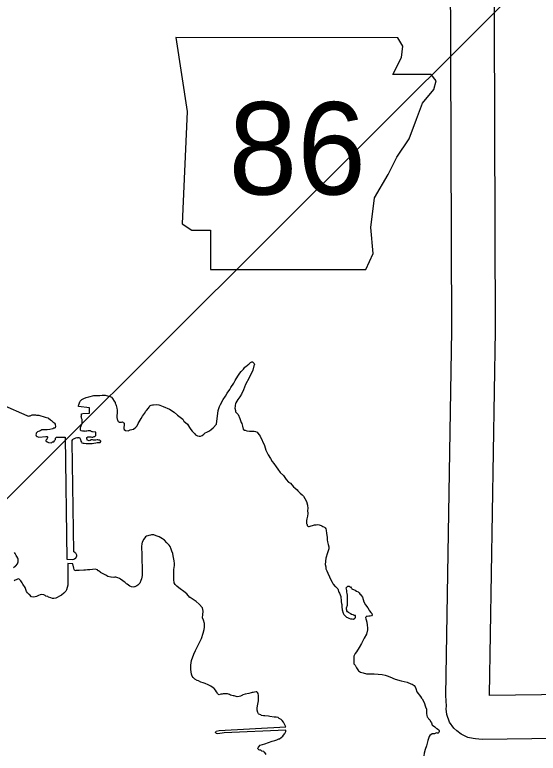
# Model space of a CAD drawing. Extents: x 982240 to 1103002, y 974866 to 1054902.
# Drawn here: x 993089 to 995781, y 1041155 to 1044953 of the extents above; entities that cross this region are included whole.
import ezdxf

# ---------------------------------------------------------------- set-up
doc = ezdxf.new("R2010")
doc.units = 0
for name, color, linetype in [('Level 10', 7, 'Continuous'), ('Level 21', 7, 'Continuous'), ('Level 9', 7, 'Continuous'), ('R_Draft', 7, 'Continuous')]:
    doc.layers.add(name, color=color, linetype=linetype)

msp = doc.modelspace()

# ---------------------------------------------------------------- linework, layer by layer
at = {"layer": 'Level 10'}
for points in [[(997535, 1041478.4), (995530.7, 1041452), (995530.5, 1041456.3), (995561.7, 1043327.4), (995554.8, 1045449.5), (993532.3, 1045386), (993520.8, 1047196.5), (993518.6, 1047217.1), (993510.8, 1047255.6), (993504, 1047271.4), (993498.3, 1047283.7), (993481.2, 1047311.6), (993449.8, 1047336.3), (993440.9, 1047341.2), (993427, 1047349.4), (993401.8, 1047358.6), (993378.8, 1047363.2), (993360.9, 1047365.2), (993338.6, 1047366.7), (991537.1, 1047360.6)], [(997538, 1041253.4), (995492.8, 1041226.5), (995458.9, 1041229.1), (995446.6, 1041230.3), (995419.3, 1041235.5), (995385.3, 1041252.6), (995363.1, 1041270), (995347.6, 1041284.6), (995324.5, 1041314.5), (995311.1, 1041353.8), (995307.9, 1041384.2), (995308.4, 1041397.6), (995305.3, 1041451.7), (995336.6, 1043328.9), (995330.6, 1045217.4), (993308.8, 1045153.9), (993296.2, 1047141.5), (991536.7, 1047135.6)]]:
    msp.add_lwpolyline(points, dxfattribs=at)
at = {"layer": 'Level 21'}
msp.add_lwpolyline([(993917.4, 1044835.9), (993974.5, 1044455.2), (993949.1, 1043877.9), (993999.9, 1043846.2), (994095, 1043846.2), (994095, 1043643.2), (994894.4, 1043643.2), (994932.5, 1043725.6), (994919.8, 1043858.9), (994938.8, 1044011.1), (995008.6, 1044131.7), (995053, 1044220.5), (995116.5, 1044315.7), (995154.5, 1044417.2), (995186.2, 1044499.6), (995243.3, 1044569.4), (995256, 1044613.8), (995230.7, 1044645.6), (995034, 1044645.6), (995078.4, 1044734.4), (995084.7, 1044791.5), (995058.4, 1044835.3)], close=True, dxfattribs=at)
at = {"layer": 'Level 9'}
for points in [[(993610, 1042944.5), (993613.5, 1042930.3), (993614.6, 1042919.1), (993615, 1042903.3), (993613.8, 1042894.2), (993614.2, 1042882.2), (993615.9, 1042874), (993617.5, 1042869.5), (993619.2, 1042864.3), (993620.8, 1042862.1), (993623.9, 1042859.2), (993626.2, 1042857.7), (993633.7, 1042858), (993638.1, 1042858.9), (993642.6, 1042859), (993646.5, 1042856.8), (993648.8, 1042855.4), (993651.1, 1042852.5), (993651.2, 1042848.7), (993650.6, 1042843.4), (993650.7, 1042840.4), (993650.2, 1042832.9), (993649.6, 1042825.4), (993651.3, 1042820.1), (993657.4, 1042815.8), (993672.5, 1042813.3), (993682.9, 1042818.8), (993700.1, 1042822.4), (993711, 1042832.5), (993717.6, 1042838.7), (993724, 1042851.6), (993739, 1042876.9), (993745.4, 1042889.1), (993755.5, 1042903), (993763.4, 1042915.2), (993767, 1042918.4), (993776.5, 1042929.9), (993780.1, 1042935.3), (993782.9, 1042942.1), (993791, 1042945.4), (993797.7, 1042947.1), (993802.2, 1042947.2), (993816.5, 1042948.4), (993830, 1042947.3), (993834.6, 1042945.9), (993852, 1042938.9), (993884, 1042925.6), (993908.5, 1042909.1), (993926.2, 1042894.5), (993952.4, 1042873.5), (993958.7, 1042863.9), (993977.2, 1042847.9), (993987.5, 1042830.2), (993993.8, 1042819.9), (994001.6, 1042811.1), (994013.9, 1042799.4), (994017.9, 1042793.5), (994027.8, 1042788.5), (994036.8, 1042786.6), (994044.3, 1042786.8), (994053.3, 1042790.1), (994061.3, 1042796.3), (994067.9, 1042803.3), (994076, 1042807.3), (994090.1, 1042813), (994098.2, 1042820), (994108.4, 1042829.3), (994125.9, 1042847.9), (994135.1, 1042917.3), (994141.9, 1042939.3), (994146.1, 1042949.2), (994161.1, 1042975.3), (994171.9, 1042992.1), (994180.5, 1043007.4), (994194.2, 1043025.9), (994200.6, 1043036.6), (994215, 1043058.8), (994222.1, 1043071.8), (994236.5, 1043094.1), (994246.5, 1043110.2), (994253.7, 1043118.7), (994264.6, 1043131), (994272.6, 1043140.3), (994275.5, 1043143.4), (994287.3, 1043153.5), (994292.4, 1043156.7), (994300.4, 1043164.4), (994308.6, 1043167.7), (994313.1, 1043167.8), (994315.4, 1043165.6), (994320.8, 1043160.5), (994321, 1043155.3), (994318.9, 1043148.4), (994312.9, 1043125.7), (994293.8, 1043086.8), (994276, 1043051.6), (994264.8, 1043025), (994254.2, 1043002.9), (994246.3, 1042989.1), (994236.3, 1042973.8), (994226.3, 1042957.7)], [(993445.4, 1042750.1), (993455.9, 1042748.1), (993467.2, 1042748.5), (993486.7, 1042749), (993495.7, 1042749.3), (993505.4, 1042751.9), (993512.8, 1042753.6), (993527.9, 1042754), (993530.7, 1042757.9), (993530.7, 1042760.9), (993526.8, 1042765.3), (993520.7, 1042765.9), (993516.2, 1042766.5), (993513.2, 1042767.1), (993505.7, 1042766.2), (993497.5, 1042765.9), (993493, 1042765), (993487.7, 1042767.1), (993486.9, 1042767.9), (993480.9, 1042766.9), (993475.8, 1042763), (993471.3, 1042762.9), (993462.9, 1042765.6), (993462.2, 1042765.6), (993461.4, 1042766.3), (993460.5, 1042770.8), (993459.7, 1042773.1), (993459.6, 1042776.8), (993459.5, 1042779.8), (993462.5, 1042780.7), (993463.9, 1042783), (993469.2, 1042783.1), (993474.4, 1042782.5), (993480.5, 1042781.9), (993485, 1042781.3), (993489.5, 1042781.5), (993494, 1042782.4), (993497.7, 1042784), (993499.9, 1042784.8), (993502.1, 1042785.6), (993505.8, 1042788.7), (993505.3, 1042806.8), (993488.7, 1042808.5), (993486.4, 1042808.4), (993480.3, 1042811.3), (993478.8, 1042812.7), (993473.5, 1042813.3), (993466.8, 1042813.1), (993460.1, 1042811.4), (993456.3, 1042811.3), (993454.8, 1042811.3), (993450.3, 1042810.4), (993446.5, 1042811), (993437.5, 1042812.2), (993429.9, 1042814.3), (993426.9, 1042816.4), (993427.5, 1042818.7), (993425.9, 1042824.7), (993427.2, 1042830), (993428.6, 1042833.8), (993432, 1042845.2), (993433.5, 1042846.7), (993434.8, 1042852.8), (993434.6, 1042858.8), (993435.2, 1042864.8), (993435, 1042871.6), (993432.5, 1042878.3), (993432.4, 1042881.3), (993430.8, 1042886.5), (993432.1, 1042891), (993431.2, 1042897), (993432.6, 1042900.1), (993439.3, 1042903.3), (993473.8, 1042904.3), (993473.8, 1042931.4), (993415.7, 1042937.9), (993416.3, 1042943.2), (993418.5, 1042947), (993421.9, 1042957.7), (993423.3, 1042962.2), (993424.7, 1042966), (993429.8, 1042970.7), (993433.4, 1042973.8), (993443, 1042980.1), (993456.4, 1042985), (993469.8, 1042989.2), (993495.9, 1042995.2), (993525.9, 1042995.4), (993537.9, 1042996.5), (993540.9, 1042996.6), (993552.9, 1042996.2), (993565, 1042993.5), (993570.3, 1042992.2), (993578.6, 1042990.9), (993585.5, 1042987.4), (993591, 1042980), (993599.6, 1042966), (993605.1, 1042958.6), (993605.2, 1042956.4), (993608.4, 1042949), (993610, 1042944.5)], [(993024.9, 1042948), (993150.5, 1042892.4), (993157.3, 1042889.6), (993163.3, 1042889.8), (993168.5, 1042891.4), (993178.2, 1042895.5), (993184.9, 1042895.7), (993194.7, 1042895.2), (993200.7, 1042894.7)], [(994226.3, 1042957.7), (994224.2, 1042952.3), (994221.4, 1042944.7), (994221.5, 1042939.5), (994221.1, 1042930.4), (994223.7, 1042918.5), (994224.6, 1042911.7), (994225.4, 1042909.5), (994237, 1042897.8), (994246.7, 1042876.3), (994249.2, 1042867.4), (994253.3, 1042857), (994255.7, 1042851), (994259.9, 1042837.6), (994264.1, 1042822.7), (994270.2, 1042817.6), (994274, 1042817), (994283.1, 1042814.2), (994284.6, 1042813.5), (994295.9, 1042811.6), (994314, 1042812.1), (994320.7, 1042812.3), (994326.8, 1042809.5), (994335.1, 1042806.8), (994338.3, 1042801.6), (994345.3, 1042792.8), (994350.8, 1042785.4), (994373.2, 1042738.7), (994380, 1042714.1), (994392.7, 1042689.7), (994404.5, 1042671.2), (994413.2, 1042656.4), (994420.3, 1042645.4), (994432.8, 1042628.5), (994442.2, 1042616), (994454, 1042599.8), (994471, 1042583), (994485.1, 1042563.8), (994496.8, 1042549.9), (994507.5, 1042543.5), (994521.5, 1042525.8), (994530, 1042519.3), (994541.5, 1042510.6), (994545.4, 1042505.5), (994550.9, 1042498.1), (994557, 1042493.1), (994567.1, 1042483.6), (994574, 1042477.8), (994581.1, 1042465.2), (994589.1, 1042449.6), (994594.2, 1042431), (994595.4, 1042414.5), (994595, 1042403.2), (994595.5, 1042388.2), (994593.6, 1042373.8), (994592.3, 1042367.8), (994590.3, 1042360.2), (994589.8, 1042352.7), (994589.3, 1042342.1), (994589.5, 1042337.6), (994590.3, 1042335.4), (994592, 1042329.4), (994592, 1042326.4), (994595.9, 1042323.5), (994599.7, 1042321.4), (994602.7, 1042322.2), (994613.1, 1042324.8), (994619.8, 1042327.2), (994625.8, 1042328.9), (994630.2, 1042329.8), (994638.5, 1042330.8), (994646, 1042331.8), (994654.3, 1042329.8), (994664.1, 1042327.1), (994667.9, 1042324.9), (994674, 1042322.1), (994680.9, 1042318.5), (994685.5, 1042314.9), (994688.7, 1042309), (994689.6, 1042302.3), (994692.4, 1042285.8), (994693.4, 1042277.6), (994695.3, 1042264.8), (994695.6, 1042253.6), (994696.7, 1042242.3), (994700.9, 1042228.1), (994703.5, 1042216.9), (994704.5, 1042208.7), (994703.8, 1042206.4), (994696.8, 1042186.7), (994689.4, 1042159.4), (994685.9, 1042126.2), (994687.8, 1042113.5), (994688.8, 1042103.7), (994692.9, 1042092.6), (994698.5, 1042080.7), (994708.1, 1042062.2), (994712.9, 1042050.3), (994720.9, 1042034.7), (994725.7, 1042025.1), (994726.4, 1042025.1)], [(993200.7, 1042894.7), (993212.8, 1042893.5), (993222.6, 1042890.8), (993234, 1042887.4), (993245.3, 1042884), (993259, 1042879.8), (993262, 1042878.4), (993272.1, 1042869.7), (993277.4, 1042866.1), (993284.4, 1042860.3), (993289, 1042856.7), (993290.5, 1042856), (993293.6, 1042852.3), (993296, 1042847.9), (993296.1, 1042844.9), (993297.8, 1042837.4), (993295.8, 1042828.3), (993292.8, 1042827.5), (993289.9, 1042826.6), (993284, 1042823.4), (993269.8, 1042820), (993254.8, 1042818.8), (993249.6, 1042817.9), (993227.8, 1042818), (993222.6, 1042814.8), (993215.2, 1042812.4), (993213.7, 1042812.3), (993205.5, 1042808.3), (993199.7, 1042802.9), (993199, 1042801.4), (993198.3, 1042798.3), (993197.7, 1042793), (993199.4, 1042787.8), (993202.5, 1042784.2), (993204, 1042783.5), (993212.4, 1042780.7), (993249.1, 1042784.8), (993254.3, 1042784.2), (993255.1, 1042783.5), (993256.6, 1042782.8), (993257.4, 1042780.5), (993257.5, 1042779), (993256.8, 1042777.5), (993254, 1042771.4), (993253.2, 1042770.6), (993251.1, 1042767.6), (993250.3, 1042766.8), (993248.9, 1042764.5), (993248.2, 1042763), (993248.2, 1042762.2), (993248.2, 1042761.5), (993250.6, 1042759.3), (993252.9, 1042757.8), (993255.9, 1042756.4), (993262, 1042753.6), (993277.1, 1042752.6), (993282.9, 1042756.5), (993288.9, 1042756.7), (993292.6, 1042761.3), (993295.4, 1042765.9), (993297.6, 1042769), (993298.3, 1042771.2), (993298.9, 1042775.8), (993299.6, 1042778), (993302.5, 1042780.4), (993348.3, 1042781), (993355.8, 1042153.3), (993385.1, 1042151.2), (993391.8, 1042152.9), (993396.2, 1042155.3), (993402.8, 1042160.7), (993403.6, 1042162.3), (993405, 1042163.1), (993406.5, 1042165.4), (993407.1, 1042170.6), (993407, 1042173.7), (993406.8, 1042178.2), (993402.2, 1042184), (993399.1, 1042186.2), (993396.8, 1042186.9), (993392.2, 1042191.3), (993383.6, 1042756.5), (993384.1, 1042764), (993387.7, 1042768.6), (993389.9, 1042771.7), (993396.6, 1042774.9), (993406.2, 1042779), (993409.2, 1042778.3), (993413.7, 1042778.4), (993418.2, 1042778.6), (993421.2, 1042778.7), (993423.5, 1042776.5), (993425.2, 1042772), (993426.8, 1042768.3), (993426.8, 1042766.8), (993427.7, 1042763.8), (993428.5, 1042760.1), (993431.7, 1042754.9), (993434, 1042752), (993440.1, 1042749.9), (993445.4, 1042750.1)], [(993892.7, 1042204), (993888.6, 1042218.1), (993882.3, 1042225.5), (993871.5, 1042237.2), (993858.3, 1042250.3), (993848.3, 1042258.3), (993831.5, 1042267.6), (993825.4, 1042270.4), (993815.5, 1042273.9), (993803.4, 1042278), (993792.1, 1042278.4), (993786.2, 1042276.7), (993777.9, 1042275.7), (993773.5, 1042274.1), (993766.1, 1042270.9), (993760.9, 1042267.7), (993752.2, 1042256.9), (993744.4, 1042241.6), (993741.7, 1042231.8), (993741.3, 1042219), (993741, 1042203.9), (993741.4, 1042189.7), (993743.6, 1042068.7), (993740.3, 1042052), (993736.8, 1042043.6), (993731.2, 1042030.7), (993726.8, 1042024.6), (993721.7, 1042019.1), (993717.3, 1042016), (993712.9, 1042014.4), (993706.9, 1042011.9), (993704, 1042011.1), (993698, 1042010.2), (993689, 1042010.6), (993681.3, 1042014.2), (993679.8, 1042014.9), (993673.7, 1042019.2), (993666.8, 1042024.3), (993662.9, 1042027.2), (993656, 1042033), (993650.6, 1042037.3), (993643.7, 1042042.4), (993632.2, 1042051), (993627.6, 1042054.7), (993618.4, 1042058.2), (993607.9, 1042060.1), (993602.6, 1042060.7), (993597.4, 1042059.8), (993583.8, 1042060.1), (993583.1, 1042060.1), (993567.9, 1042064.2), (993556.5, 1042070.6), (993542.8, 1042077.7), (993529.8, 1042084.8), (993529, 1042086.3), (993519.8, 1042092.8), (993516, 1042094.2), (993513.6, 1042097.9), (993501.5, 1042101.3), (993488.8, 1042100.1), (993475.3, 1042099), (993463.3, 1042098.6), (993452.1, 1042096.8), (993443.1, 1042096.5), (993419.8, 1042095.1), (993402.6, 1042094.6), (993398.1, 1042093.7), (993394.9, 1042099.6), (993391.7, 1042107), (993387.3, 1042129.4), (993362.4, 1042131.7), (993361.2, 1042019.6), (993358.6, 1042008.3), (993354.4, 1041996.1), (993350.9, 1041988.5), (993340.7, 1041977.7), (993329.7, 1041969.1), (993318.6, 1041963.5), (993306, 1041956.3), (993299.4, 1041952.4), (993289.7, 1041951.3), (993282.1, 1041951.8), (993273.8, 1041954.6), (993262.5, 1041957.3), (993258.6, 1041960.9), (993248.8, 1041963.6), (993244.9, 1041965.8), (993237.3, 1041969.3), (993224.5, 1041971.9), (993220, 1041970.3), (993211.1, 1041966.3), (993203.7, 1041962.3), (993200, 1041961.4), (993194.1, 1041959), (993182.8, 1041957.9), (993174.5, 1041959.2), (993164.4, 1041970.9), (993160.6, 1041973), (993153.6, 1041981.1), (993148.9, 1041987.7), (993141.6, 1042007)], [(993082.9, 1042110.6), (993091, 1042116.8), (993094.6, 1042119.9), (993101.9, 1042129.2), (993106.8, 1042139.1), (993106.6, 1042147.4), (993105.7, 1042153.4), (993104, 1042158.6), (993099.3, 1042166.7), (993096.1, 1042171.9), (993093.7, 1042176.3), (993089.8, 1042182.2), (993086.6, 1042187.4)], [(994400.5, 1041344.6), (994394.5, 1041345.2), (994374.9, 1041346.8), (994367.4, 1041347.4), (994357.5, 1041350.1), (994353.7, 1041352.2), (994343.8, 1041356.4), (994341.5, 1041357.9), (994339.1, 1041365.3), (994334.9, 1041377.2), (994336.1, 1041389.3), (994338.5, 1041408.2), (994342.5, 1041425.6), (994342.8, 1041442.9), (994341.7, 1041452.6), (994340.7, 1041462.4), (994339.9, 1041463.1), (994337.5, 1041468.3), (994335.2, 1041469.7), (994332.9, 1041471.2), (994330.6, 1041471.9), (994322.4, 1041470.1), (994314.2, 1041468.4), (994310.5, 1041468.2), (994305.2, 1041466.6), (994293.3, 1041463.2), (994273.9, 1041458.9), (994262, 1041454.8), (994259.8, 1041453.9), (994249.4, 1041449.1), (994242.8, 1041446.7), (994232.3, 1041445.6), (994217.1, 1041449.7), (994211.9, 1041450.3), (994198.2, 1041454.4), (994192.9, 1041456.5), (994183, 1041460.7), (994182.3, 1041460.7), (994168, 1041461), (994161.2, 1041461.5), (994156, 1041459.9), (994149.3, 1041458.2), (994140.3, 1041455.6), (994137.3, 1041457.1), (994135.8, 1041457.8), (994133.4, 1041460.7), (994131.8, 1041464.4), (994126.4, 1041471), (994121.6, 1041479.9), (994113.8, 1041487.9), (994108.5, 1041492.3), (994097.7, 1041499.5), (994084, 1041506.6), (994068.7, 1041514.4), (994058.1, 1041517.8), (994045.3, 1041521.2), (994033.8, 1041526.9), (994026.2, 1041529.7), (994014.8, 1041536.1), (994007, 1041544.9), (994001.5, 1041552.3), (993997.5, 1041562.7), (993993.8, 1041585.1), (993994.6, 1041608.4), (993998.4, 1041631.9), (994010.2, 1041665.3), (994017.9, 1041684.3), (994034.3, 1041714.2), (994048.3, 1041746.2), (994057.3, 1041772), (994062, 1041791.7), (994063.9, 1041804.5), (994064, 1041823.3), (994059.8, 1041839.7), (994055, 1041850.9), (994054.9, 1041853.1), (994055.2, 1041866.7), (994057.7, 1041885.6), (994054.2, 1041902.7), (994037.8, 1041922.6), (994022.4, 1041935.6), (993990.3, 1041955.7), (993989.5, 1041955.7), (993973.1, 1041975.5), (993957.8, 1041986.3), (993939.3, 1042000.8), (993931.7, 1042006.6), (993921.6, 1042015.3), (993913.9, 1042022.6), (993909.1, 1042032.3), (993906.4, 1042048), (993907.5, 1042062.3), (993906.7, 1042087.1), (993906.3, 1042100.6), (993909.5, 1042120.3), (993910.7, 1042130.8), (993908.8, 1042145), (993903.5, 1042170.5), (993901.6, 1042182.4), (993896, 1042195), (993892.7, 1042204)], [(993141.6, 1042007), (993130.5, 1042024.8), (993127.3, 1042031.4), (993119.5, 1042041.7), (993114.8, 1042047.6), (993108.7, 1042051.9), (993103.4, 1042051), (993095.3, 1042047.8), (993090.1, 1042045.4), (993085.7, 1042041.5)], [(994726.4, 1042025.1), (994735.8, 1042013.4), (994739.6, 1042011.2), (994749.7, 1042000.3), (994756.2, 1041983.2), (994759.4, 1041978.7), (994765.2, 1041960.9), (994766.1, 1041954.1), (994767.2, 1041944.4), (994768.2, 1041935.4), (994770, 1041923.4), (994770.1, 1041922.7), (994770.5, 1041908.4), (994773.2, 1041892.7), (994777.5, 1041876.3), (994781.4, 1041868.9), (994786.1, 1041864.5), (994795.3, 1041855.7), (994799.2, 1041853.6), (994807.5, 1041849.3), (994815.1, 1041846.6), (994824.2, 1041846.1), (994830.2, 1041845.5), (994837.6, 1041849.5), (994840.4, 1041854.1), (994840.9, 1041863.1), (994836.4, 1041863.7), (994834.1, 1041864.4), (994831.8, 1041865.8), (994828.8, 1041866.5), (994822.7, 1041868.6), (994822, 1041868.6), (994819, 1041869.2), (994818.1, 1041872.2), (994809.7, 1041876.5), (994808.2, 1041877.2), (994805.1, 1041879.3), (994799.8, 1041882.9), (994797.4, 1041887.4), (994796.5, 1041891.1), (994794.9, 1041897.1), (994795.4, 1041902.4), (994799.5, 1041916), (994800, 1041925.1), (994800.4, 1041937.1), (994800.3, 1041940.9), (994800, 1041950.6), (994800.2, 1041968.7), (994797.7, 1041977.6), (994796.8, 1041984.4), (994796.5, 1041991.9), (994793.8, 1042006.8), (994796, 1042009.9), (994801.1, 1042013.8), (994804.1, 1042013.9), (994807.9, 1042014), (994812.5, 1042011.9), (994816.3, 1042010.5), (994818.6, 1042006.8), (994820.2, 1042003.9), (994822.6, 1042000.2), (994826.4, 1041998.8), (994831.7, 1041996.7), (994839.3, 1041993.9), (994846.9, 1041989.6), (994854.6, 1041985.3), (994860.7, 1041980.3), (994864.7, 1041972.1), (994864.7, 1041971.4), (994867, 1041971.4), (994876.4, 1041957.4), (994883.9, 1041933.6), (994891.9, 1041918), (994904.3, 1041902.6), (994911.5, 1041890.8), (994913.8, 1041887.1), (994920.8, 1041879.8), (994924.7, 1041873.9), (994926.4, 1041866.4), (994923.6, 1041861.1), (994916.9, 1041860.1), (994910.1, 1041859.9), (994901.1, 1041858.9), (994895.9, 1041858), (994895.2, 1041856.5), (994893.1, 1041852.6), (994894.8, 1041845.9), (994896.4, 1041840.7), (994899, 1041829.5), (994901.7, 1041813.8), (994902.9, 1041801), (994903.2, 1041789.8), (994897.1, 1041768.5), (994885.7, 1041747.1), (994871.5, 1041720.4), (994860.1, 1041699), (994845.7, 1041676.8), (994840, 1041667.6), (994832.1, 1041653.8), (994832.2, 1041653), (994832, 1041632.7)], [(994832, 1041632.7), (994832.4, 1041618.5), (994833.3, 1041615.5), (994839.5, 1041607.4), (994846.7, 1041594.8), (994856.2, 1041578.6), (994866.9, 1041572.9), (994880.5, 1041568), (994897.9, 1041563.3), (994918.2, 1041563.9), (994937.7, 1041563), (994957.3, 1041562), (994977.6, 1041560.4), (994993.5, 1041557.1), (995004.1, 1041553.7), (995018.5, 1041548.8), (995045.2, 1041536.1), (995076.2, 1041528), (995106.5, 1041520.6), (995126.2, 1041513), (995132.3, 1041510.1), (995142.3, 1041504.4), (995147.8, 1041496.3), (995151.8, 1041487.4), (995157.5, 1041471), (995174.8, 1041446.7), (995181.1, 1041437.9), (995183.4, 1041434.2), (995194.5, 1041415.7), (995201.1, 1041394.1), (995206, 1041381.5), (995205.6, 1041371.7), (995206.6, 1041360.4), (995208.5, 1041350), (995210.2, 1041342.5), (995212.5, 1041338.8), (995216.5, 1041332.9), (995220.3, 1041330), (995224.2, 1041326.4), (995227.4, 1041319), (995232.1, 1041312.3), (995236.2, 1041299.7), (995237, 1041299.7), (995248.5, 1041291), (995257.8, 1041283), (995259.3, 1041282.3), (995268.5, 1041277.3), (995270, 1041274.4), (995271.6, 1041272.2), (995271.8, 1041266.9), (995270.4, 1041262.3), (995266.8, 1041258.5), (995262.2, 1041259.1), (995257, 1041259.7), (995251.8, 1041257.3), (995248.1, 1041255.7), (995236.1, 1041254.5), (995223.6, 1041246.7), (995220.7, 1041241.3), (995213.8, 1041220), (995207.1, 1041192.8), (995198.7, 1041174.5), (995194, 1041156.3), (995192.9, 1041142)], [(994382.3, 1041149.3), (994375.3, 1041158.9), (994371.4, 1041161), (994369.1, 1041164.7), (994359.2, 1041166.7), (994354.6, 1041170.3), (994348.6, 1041171.6), (994344.8, 1041173), (994342.5, 1041175.2), (994340.9, 1041175.9), (994339.3, 1041179.6), (994340, 1041184.1), (994342.1, 1041186.4), (994350.1, 1041196.5), (994375.4, 1041204), (994413.3, 1041217.2), (994426, 1041220.5), (994437.2, 1041223.9), (994447.5, 1041228.7), (994449.8, 1041229.5), (994458.6, 1041235.8), (994468.1, 1041243.6), (994476, 1041254.4), (994477.5, 1041256.7), (994483.2, 1041267.4), (994482.2, 1041274.1), (994165.7, 1041259.4), (994132.8, 1041255.4), (994126.7, 1041256.7), (994125.2, 1041258.2), (994122.9, 1041260.4), (994120.6, 1041261.8), (994121.3, 1041263.3), (994122, 1041264.8), (994124.2, 1041267.9), (994139.8, 1041271.4), (994482.5, 1041290.7), (994476.1, 1041304), (994475.3, 1041305.5), (994470.5, 1041314.4), (994463.5, 1041323.2), (994458.1, 1041328.3), (994448.9, 1041334), (994443.5, 1041339.1), (994433.7, 1041341.1), (994423.1, 1041341.5), (994400.5, 1041344.6)]]:
    msp.add_lwpolyline(points, dxfattribs=at)
at = {"layer": 'R_Draft'}
msp.add_lwpolyline([(991692.3, 1041115.1), (1004137.6, 1053519.7), (991630.8, 1045465.2)], dxfattribs=at)

# ---------------------------------------------------------------- texts
at = {"layer": 'Level 21'}
msp.add_text('86', height=475.2, dxfattribs=at).set_placement((994188.1, 1044028.9))

doc.saveas('drawing.dxf')
